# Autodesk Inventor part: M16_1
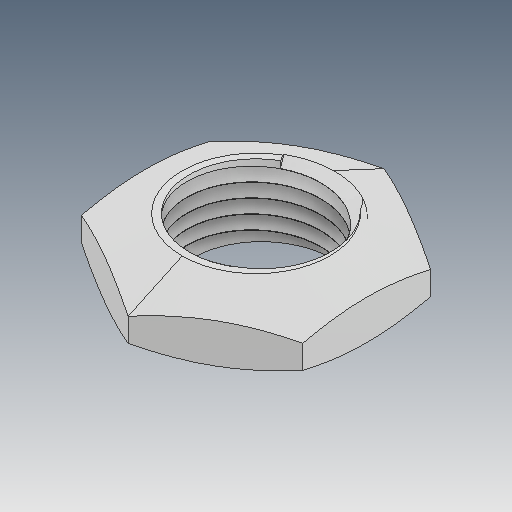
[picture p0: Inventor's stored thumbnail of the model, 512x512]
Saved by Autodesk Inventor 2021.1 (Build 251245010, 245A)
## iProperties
Created: 2021-05
Part Number: M16_1
Material: Ogólny
Document SubType Name: Modeling
Designer: user
Density: 1 g/cm^3
Appearance: Domyślna
Author: user
Revision Number: ÈÎºÎ
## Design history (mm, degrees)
feature "ÊäÈë1"
node "Bryła1"
